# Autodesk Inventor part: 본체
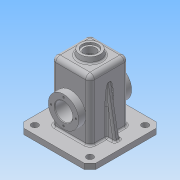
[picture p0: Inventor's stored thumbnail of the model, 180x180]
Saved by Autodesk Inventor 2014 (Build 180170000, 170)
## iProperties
Created: 2016-02
Part Number: 본체
Material: Generic
Document SubType Name: Modeling
Designer: User
Density: 1 g/cm^3
Appearance: Default
Author: User
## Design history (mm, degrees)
sketch "스케치1"
  geometry: L1 (35, 35)-(-35, 35); L2 (-35, 35)-(-35, -35); L3 (-35, -35)-(35, -35); L4 (35, -35)-(35, 35); L5 (-35, 35)-(35, -35); 2 further points
  constraints: 10 end point, 2 parallel, 1 coincident, 1 horizontal, 1 midpoint, 1 perpendicular
  dimensions: "d0" = 70 distance of L1.start L1.end; "d1" = 70 distance of L1.end L2.end
extrude "돌출1" new body sketch "스케치1" distance "d2" = 120; taper "d3" = 0 deg
feature "쉘1" dims "d4" = 5
sketch "스케치3"
  geometry: L1 (-35, 35)-(35, 35) reference; L2 (-35, -35)-(-35, 35) reference; L3 (35, -35)-(-35, -35) reference; L4 (35, 35)-(35, -35) reference; L5 (-65, 65)-(65, 65); L6 (65, 65)-(65, -65); L7 (65, -65)-(-65, -65); L8 (-65, -65)-(-65, 65); L9 (-65, 65)-(65, -65); 2 further points
  constraints: 10 end point, 2 parallel, 1 coincident, 1 horizontal, 1 midpoint, 1 perpendicular
  dimensions: "d5" = 130 distance of L5.start L5.end; "d6" = 130 distance of L5.end L6.end
extrude "돌출2" join sketch "스케치3" distance "d7" = 10; taper "d8" = 0 deg
fillet "모깎기1" dims "d9" = 8
sketch "스케치5"
  geometry: L1 (30, 0)-(30, 115) reference; L2 (30, 115)-(-30, 115) reference; L3 (-30, 115)-(-30, 0) reference; L4 (-30, 0)-(-65, 0) reference; L5 (-65, 0)-(-65, 10) reference; L6 (-65, 10)-(-35, 10) reference; L7 (-35, 10)-(-35, 120) reference; L8 (-35, 120)-(35, 120) reference; L9 (35, 120)-(35, 10) reference; L10 (35, 10)-(65, 10) reference; L11 (65, 10)-(65, 0) reference; L12 (65, 0)-(30, 0) reference; L13 (0, 120)-(-20, 120); L14 (-20, 120)-(-20, 130); L15 (-18.237, 130)-(0, 130); L16 (0, 130)-(0, 120); L17 (-20, 120)-(-18.237, 130); 1 further point
  constraints: 10 end point, 2 parallel, 1 horizontal, 1 midpoint, 1 perpendicular
  dimensions: "d20" = 40 diameter of L13.end L16; "d21" = 10 deg angle of L14 L17; "d22" = 10 distance between parallel lines of L13 L15
revolve "회전1" sketch "스케치5" stored, may be unused: angle "d23" = 90 deg
sketch "스케치6"
  geometry: C1 r 18.237 at (0, 0) reference
hole "구멍1" sketch "스케치6" at (0, 0) diameter "d24" = 21; stored, may be unused: countersink angle "d28" = 90 deg, drill point angle "d30" = 0 deg; dims "d25" = 6, "d26" = 28, "d27" = 4, "d29" = 30
sketch "스케치7"
  geometry: L1 (0, -110)-(54, -110) reference; L2 (27, -120)-(27, -65); C1 r 27.5 at (27, -65)
  constraints: 2 end point, 1 centre point, 1 coincident, 1 perpendicular
  dimensions: "d31" = 55 distance of L2.start L2.end; "d32" = 55 diameter of C1
extrude "돌출3" join sketch "스케치7" distance "d33" = 13; taper "d34" = 0 deg
sketch "스케치8"
  geometry: L1 (-30, 115)-(-30, 0) reference; L2 (-30, 0)-(-65, 0) reference; L3 (-65, 0)-(-65, 10) reference; L4 (-65, 10)-(-35, 10) reference; L5 (-35, 10)-(-35, 27.5) reference; L6 (-35, 27.5)-(-48, 27.5) reference; L7 (-48, 27.5)-(-48, 82.5) reference; L8 (-48, 82.5)-(-35, 82.5) reference; L9 (-35, 82.5)-(-35, 120) reference; L10 (-35, 120)-(-20, 120) reference; L11 (-20, 120)-(-18.237, 130) reference; L12 (-18.237, 130)-(-14, 130) reference; L13 (-14, 130)-(-14, 126) reference; L14 (-14, 126)-(-10.5, 126) reference; L15 (-10.5, 126)-(-10.5, 115) reference; L16 (-10.5, 115)-(-30, 115) reference; L17 (30, 0)-(30, 115) reference; L18 (30, 115)-(10.5, 115) reference; L19 (10.5, 115)-(10.5, 126) reference; L20 (10.5, 126)-(14, 126) reference; L21 (14, 126)-(14, 130) reference; L22 (14, 130)-(18.237, 130) reference; L23 (18.237, 130)-(20, 120) reference; L24 (20, 120)-(35, 120) reference; L25 (35, 120)-(35, 10) reference; L26 (35, 10)-(65, 10) reference; L27 (65, 10)-(65, 0) reference; L28 (65, 0)-(30, 0) reference; L29 (-35, 82.5)-(-30, 82.5); L30 (-30, 82.5)-(-23, 75.5); L31 (-23, 75.5)-(-23, 55); L32 (-48, 82.5)-(-48, 27.5) reference; L33 (-48, 55)-(-23, 55); 1 further point
  constraints: 8 end point, 2 parallel, 1 midpoint, 1 perpendicular, 1 point on line
  dimensions: "d35" = 135 deg angle of L1 L30; "d36" = 7 distance between parallel lines of L1 L31
revolve "회전2" sketch "스케치8" stored, may be unused: angle "d37" = 90 deg
sketch "스케치9"
  geometry: C1 r 27.5 at (0, 0) reference; 1 further point
hole "구멍2" sketch "스케치9" at (0, 0) diameter "d38" = 32; stored, may be unused: countersink angle "d42" = 90 deg, drill point angle "d44" = 0 deg; dims "d39" = 6, "d40" = 4, "d41" = 2, "d43" = 8
sketch "스케치10" dims "d45" = 45
  geometry: C1 r 16 at (0, 0) reference; C2 r 27.5 at (0, 0) reference; 3 further points
  constraints: 2 vertical alignment, 1 coincident, 2 other
hole "구멍3" sketch "스케치10" at (0, -22.5) diameter "d46" = 3.242; stored, may be unused: countersink angle "d50" = 82 deg, drill point angle "d52" = 118 deg; dims "d47" = 8, "d48" = 3.023, "d49" = 2, "d51" = 10
sketch "스케치12"
  geometry: L1 (-30, 115)-(-30, 0) reference; L2 (-30, 0)-(-65, 0) reference; L3 (-65, 0)-(-65, 10) reference; L4 (-65, 10)-(-35, 10) reference; L5 (-35, 10)-(-35, 120) reference; L6 (-35, 120)-(-20, 120) reference; L7 (-20, 120)-(-18.237, 130) reference; L8 (-18.237, 130)-(-14, 130) reference; L9 (-14, 130)-(-14, 126) reference; L10 (-14, 126)-(-10.5, 126) reference; L11 (-10.5, 126)-(-10.5, 115) reference; L12 (-10.5, 115)-(-30, 115) reference; L13 (30, 0)-(30, 115) reference; L14 (30, 115)-(10.5, 115) reference; L15 (10.5, 115)-(10.5, 126) reference; L16 (10.5, 126)-(14, 126) reference; L17 (14, 126)-(14, 130) reference; L18 (14, 130)-(18.237, 130) reference; L19 (18.237, 130)-(20, 120) reference; L20 (20, 120)-(35, 120) reference; L21 (35, 120)-(35, 10) reference; L22 (35, 10)-(65, 10) reference; L23 (65, 10)-(65, 0) reference; L24 (65, 0)-(30, 0) reference; L25 (65, 10)-(-65, 10) reference; L26 (-50, 10)-(-35, 95.069); 1 further point
  constraints: 2 end point, 2 point on line
  dimensions: "d56" = 10 deg angle of L5 L26; "d57" = 15 horizontal distance of L26.start L2.end
feature "리브1" sketch "스케치12" dims "d58" = 1, "d59" = 10, "d60" = 0, "d61" = 0, "d62" = 1, "d63" = 1
chamfer "모따기1" distance "d64" = 10; stored, may be unused: second distance "d65" = 2, angle "d66" = 45 deg
sketch "스케치13"
  geometry: L1 (-65, 55)-(-65, -55) reference; L2 (55, 65)-(-55, 65) reference; C1 r 6 at (-50, 50); 1 further point
  constraints: 1 centre point
  dimensions: "d67" = 15 distance from line of L1 C1.centre; "d68" = 15 distance from line of L2 C1.centre; "d69" = 12 diameter of C1
extrude "돌출4" cut sketch "스케치13" stored distance "d70" = 13; taper "d71" = 0 deg
fillet "모깎기2" dims "d78" = 8
fillet "모깎기3" dims "d79" = 3
chamfer "모따기2" distance "d80" = 1; stored, may be unused: second distance "d81" = 2, angle "d82" = 45 deg
fillet "모깎기5" dims "d84" = 3
node "솔리드1"
mirror "대칭1"
pattern_circular "원형 패턴1" dims angle "d54" = 360 deg
mirror "대칭2"
mirror "대칭3"
pattern_linear "직사각형 패턴1" dims "d74" = 100
pattern_linear "직사각형 패턴2"
node "절단 모서리 투영1"
node "절단 모서리 투영2"
node "절단 모서리 투영3"
